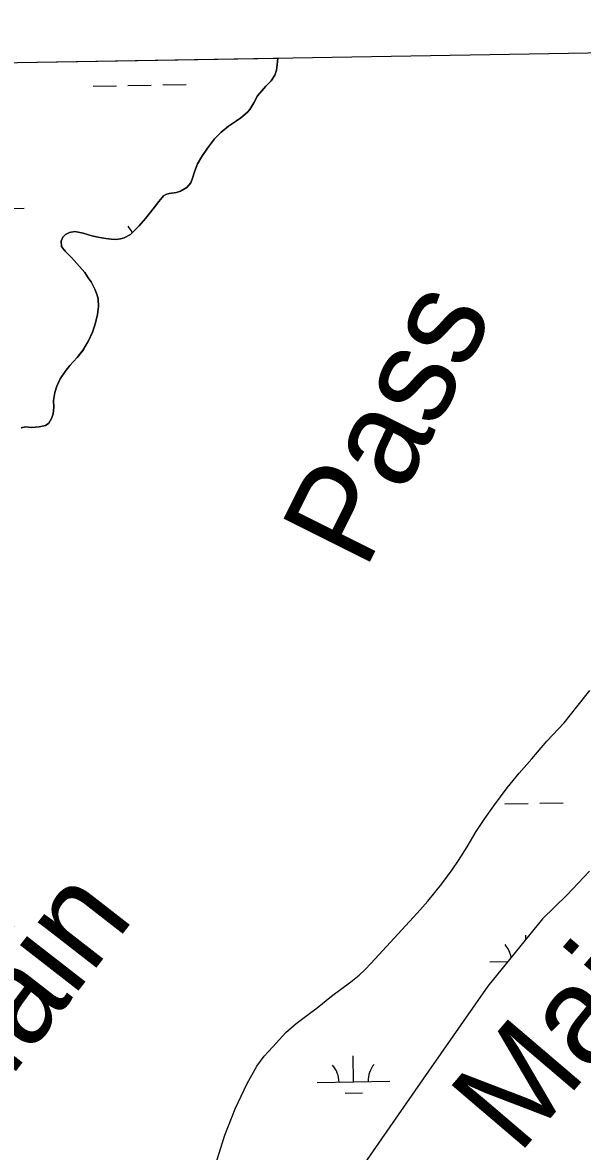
# Model space of a CAD drawing. Extents: x 3892998 to 3931244, y 278583 to 304547.
# Drawn here: x 3922438 to 3923209, y 301137 to 302691 of the extents above; entities that cross this region are included whole.
import ezdxf

# ---------------------------------------------------------------- set-up
doc = ezdxf.new("R2010")
doc.units = 0
for name, color, linetype in [('V-GRID-FRAM', 7, 'Continuous'), ('V-RIVR-IDEN', 7, 'Continuous'), ('V-TOPO-SHOR', 7, 'Continuous'), ('V-WETL-SWMP', 7, 'Continuous')]:
    doc.layers.add(name, color=color, linetype=linetype)

msp = doc.modelspace()

# ---------------------------------------------------------------- linework, layer by layer
at = {"layer": 'V-GRID-FRAM'}
msp.add_lwpolyline([(3896958.4, 302195.2), (3928823.6, 302746.7), (3929146.3, 284567.1), (3897265.1, 284015.2), (3896958.4, 302195.2)], dxfattribs=at)
at = {"layer": 'V-TOPO-SHOR'}
for points in [[(3922477.7, 302145.9), (3922479.7, 302152.3), (3922480.6, 302161.6), (3922480.2, 302170.5), (3922482.1, 302181.6), (3922485.1, 302190.5), (3922489.5, 302200.4), (3922496.3, 302210.7), (3922502.9, 302218.7), (3922512.7, 302229.7), (3922521.2, 302240.3), (3922528.1, 302252), (3922534.2, 302264.8), (3922537.7, 302275.9), (3922540.7, 302288.9), (3922542.3, 302300.2), (3922541.8, 302310.7), (3922540.1, 302317.3), (3922537.4, 302323.8), (3922532, 302334), (3922528.2, 302339.8), (3922523.4, 302347), (3922505.1, 302367.8), (3922496.5, 302376.1), (3922491.5, 302382.8), (3922490.8, 302389.9), (3922493.1, 302395.7), (3922496.9, 302399.5), (3922502.5, 302402.2), (3922509.5, 302403.4), (3922521.4, 302400.9), (3922533.3, 302397.4), (3922544.2, 302395), (3922552.4, 302393.9), (3922559.7, 302392.7), (3922566.1, 302392.2), (3922572.4, 302393.1), (3922577.8, 302394.8), (3922586.3, 302399.4), (3922598.4, 302411), (3922607, 302421.3), (3922619.3, 302436.8), (3922625.2, 302444.8), (3922630.1, 302450.4), (3922632, 302452.6), (3922635, 302454.4), (3922639.5, 302455.6), (3922649.5, 302457.1), (3922655.3, 302459), (3922663.8, 302464.1), (3922669.3, 302470.6), (3922671.1, 302475.3), (3922674.8, 302487), (3922678.8, 302496.7), (3922684.8, 302506.9), (3922692.5, 302518.3), (3922702.2, 302530.8), (3922710.8, 302539.7), (3922721.5, 302548.3), (3922732.2, 302555.6), (3922738.2, 302559.9), (3922747.5, 302567.6), (3922750.8, 302571.6), (3922756.3, 302580.6), (3922761.4, 302590.3), (3922767, 302597.2), (3922772.9, 302603.6), (3922780, 302611.1), (3922784.9, 302618.5), (3922787.3, 302625.6), (3922788.5, 302632.8), (3922789.1, 302642), (3922789.1, 302642.3)], [(3922436, 302132.9), (3922441.8, 302134.3), (3922450.3, 302133.6), (3922460.5, 302134.3), (3922469.5, 302136.3), (3922473.8, 302139.5), (3922477.7, 302145.9)], [(3922981.2, 301464.5), (3922995.7, 301481.3), (3923015.2, 301505.3), (3923029.4, 301524.5), (3923037.9, 301537), (3923049.9, 301555.9), (3923062.4, 301577.1), (3923074.1, 301594.9), (3923086.8, 301612.7), (3923105.2, 301637.3), (3923121.8, 301657.6), (3923138.9, 301677.4), (3923159.5, 301701.7), (3923183.6, 301727), (3923201, 301748.7), (3923218.7, 301771.4)], [(3923153.5, 301457), (3923187, 301489.4), (3923218.2, 301522.5)], [(3922700.6, 301109.3), (3922716.2, 301159), (3922730.3, 301195.4), (3922746.8, 301230.2), (3922760.1, 301253.8), (3922770.4, 301267.9), (3922782.2, 301280.8), (3922800.1, 301300.3), (3922814.6, 301312.7), (3922829.4, 301323.8), (3922843.4, 301334.2), (3922863, 301350.2), (3922889.6, 301370.1), (3922901.3, 301379.5), (3922909.4, 301387.2), (3922917.5, 301395.6), (3922928.4, 301407.1), (3922981.2, 301464.5)], [(3923153.5, 301457), (3923078.3, 301364.3), (3922996.9, 301246.9), (3922897.6, 301104.2)]]:
    msp.add_lwpolyline(points, dxfattribs=at)
at = {"layer": 'V-WETL-SWMP'}
for p, q in [((3922018.6, 302628.9), (3922789.1, 302642.3)), ((3922788.5, 302632.8), (3922787.3, 302625.6)), ((3922789.1, 302642), (3922788.5, 302632.8)), ((3922789.1, 302642.3), (3922789.1, 302642)), ((3922784.9, 302618.5), (3922780, 302611.1)), ((3922787.3, 302625.6), (3922784.9, 302618.5)), ((3922534.9, 302603.6), (3922566.9, 302604.1)), ((3922582.9, 302604.4), (3922614.9, 302604.9)), ((3922630.9, 302605.2), (3922662.9, 302605.8)), ((3922772.9, 302603.6), (3922767, 302597.2)), ((3922780, 302611.1), (3922772.9, 302603.6)), ((3922761.4, 302590.3), (3922756.3, 302580.6)), ((3922767, 302597.2), (3922761.4, 302590.3)), ((3922750.8, 302571.6), (3922747.5, 302567.6)), ((3922756.3, 302580.6), (3922750.8, 302571.6)), ((3922732.2, 302555.6), (3922721.5, 302548.3)), ((3922738.2, 302559.9), (3922732.2, 302555.6)), ((3922747.5, 302567.6), (3922738.2, 302559.9)), ((3922710.8, 302539.7), (3922702.2, 302530.8)), ((3922721.5, 302548.3), (3922710.8, 302539.7)), ((3922702.2, 302530.8), (3922692.5, 302518.3)), ((3922692.5, 302518.3), (3922684.8, 302506.9)), ((3922678.8, 302496.7), (3922674.8, 302487)), ((3922684.8, 302506.9), (3922678.8, 302496.7)), ((3922674.8, 302487), (3922671.1, 302475.3)), ((3922663.8, 302464.1), (3922655.3, 302459)), ((3922669.3, 302470.6), (3922663.8, 302464.1)), ((3922671.1, 302475.3), (3922669.3, 302470.6)), ((3922630.1, 302450.4), (3922625.2, 302444.8)), ((3922632, 302452.6), (3922630.1, 302450.4)), ((3922635, 302454.4), (3922632, 302452.6)), ((3922639.5, 302455.6), (3922635, 302454.4)), ((3922649.5, 302457.1), (3922639.5, 302455.6)), ((3922655.3, 302459), (3922649.5, 302457.1)), ((3922407.9, 302434.8), (3922439.9, 302435.4)), ((3922619.3, 302436.8), (3922607, 302421.3)), ((3922625.2, 302444.8), (3922619.3, 302436.8)), ((3922607, 302421.3), (3922598.4, 302411)), ((3922496.9, 302399.5), (3922493.1, 302395.7)), ((3922502.5, 302402.2), (3922496.9, 302399.5)), ((3922509.5, 302403.4), (3922502.5, 302402.2)), ((3922521.4, 302400.9), (3922509.5, 302403.4)), ((3922533.3, 302397.4), (3922521.4, 302400.9)), ((3922586.3, 302399.4), (3922577.8, 302394.8)), ((3922598.4, 302411), (3922586.3, 302399.4)), ((3922493.1, 302395.7), (3922490.8, 302389.9)), ((3922490.8, 302389.9), (3922491.5, 302382.8)), ((3922544.2, 302395), (3922533.3, 302397.4)), ((3922552.4, 302393.9), (3922544.2, 302395)), ((3922559.7, 302392.7), (3922552.4, 302393.9)), ((3922566.1, 302392.2), (3922559.7, 302392.7)), ((3922572.4, 302393.1), (3922566.1, 302392.2)), ((3922577.8, 302394.8), (3922572.4, 302393.1)), ((3922491.5, 302382.8), (3922496.5, 302376.1)), ((3922496.5, 302376.1), (3922505.1, 302367.8)), ((3922505.1, 302367.8), (3922523.4, 302347)), ((3922523.4, 302347), (3922528.2, 302339.8)), ((3922528.2, 302339.8), (3922532, 302334)), ((3922532, 302334), (3922537.4, 302323.8)), ((3922537.4, 302323.8), (3922540.1, 302317.3)), ((3922540.1, 302317.3), (3922541.8, 302310.7)), ((3922541.8, 302310.7), (3922542.3, 302300.2)), ((3922542.3, 302300.2), (3922540.7, 302288.9)), ((3922537.7, 302275.9), (3922534.2, 302264.8)), ((3922540.7, 302288.9), (3922537.7, 302275.9)), ((3922534.2, 302264.8), (3922528.1, 302252)), ((3922528.1, 302252), (3922521.2, 302240.2)), ((3922512.7, 302229.7), (3922502.9, 302218.7)), ((3922521.2, 302240.2), (3922512.7, 302229.7)), ((3922502.9, 302218.7), (3922496.3, 302210.7)), ((3922489.5, 302200.4), (3922485.1, 302190.5)), ((3922496.3, 302210.7), (3922489.5, 302200.4)), ((3922482.1, 302181.6), (3922480.2, 302170.5)), ((3922485.1, 302190.5), (3922482.1, 302181.6)), ((3922480.2, 302170.5), (3922480.6, 302161.6)), ((3922479.7, 302152.3), (3922477.7, 302145.9)), ((3922480.6, 302161.6), (3922479.7, 302152.3)), ((3922469.5, 302136.3), (3922460.5, 302134.3)), ((3922473.8, 302139.5), (3922469.5, 302136.3)), ((3922477.7, 302145.9), (3922473.8, 302139.5)), ((3922441.8, 302134.3), (3922436, 302132.9)), ((3922450.3, 302133.6), (3922441.8, 302134.3)), ((3922460.5, 302134.3), (3922450.3, 302133.6)), ((3923201, 301748.7), (3923218.7, 301771.4)), ((3923183.6, 301727), (3923201, 301748.7)), ((3923159.5, 301701.7), (3923183.6, 301727)), ((3923138.9, 301677.4), (3923159.5, 301701.7)), ((3923121.8, 301657.6), (3923138.9, 301677.4)), ((3923105.2, 301637.3), (3923121.8, 301657.6)), ((3923086.8, 301612.7), (3923105.2, 301637.3)), ((3923074.1, 301594.9), (3923086.8, 301612.7)), ((3923102, 301615.2), (3923134, 301615.7)), ((3923150, 301616), (3923182, 301616.6)), ((3923062.4, 301577.1), (3923074.1, 301594.9)), ((3923049.9, 301555.9), (3923062.4, 301577.1)), ((3923037.9, 301537), (3923049.9, 301555.9)), ((3923029.4, 301524.5), (3923037.9, 301537)), ((3923015.2, 301505.3), (3923029.4, 301524.5)), ((3923218.2, 301522.5), (3923187, 301489.4)), ((3922995.7, 301481.3), (3923015.2, 301505.3)), ((3923187, 301489.4), (3923153.5, 301457)), ((3922981.2, 301464.5), (3922995.7, 301481.3)), ((3922928.4, 301407.1), (3922981.2, 301464.5)), ((3923153.5, 301457), (3923078.3, 301364.3)), ((3923130.7, 301428.9), (3923130.6, 301434.4)), ((3922917.5, 301395.6), (3922928.4, 301407.1)), ((3922909.4, 301387.2), (3922917.5, 301395.6)), ((3923081.2, 301397.6), (3923105.6, 301398)), ((3922889.6, 301370.1), (3922901.3, 301379.5)), ((3922901.3, 301379.5), (3922909.4, 301387.2)), ((3922863, 301350.2), (3922889.6, 301370.1)), ((3923078.3, 301364.3), (3922996.9, 301246.9)), ((3922843.4, 301334.2), (3922863, 301350.2)), ((3922829.4, 301323.8), (3922843.4, 301334.2)), ((3922800.1, 301300.3), (3922814.6, 301312.7)), ((3922814.6, 301312.7), (3922829.4, 301323.8)), ((3922782.2, 301280.8), (3922800.1, 301300.3)), ((3922770.4, 301267.9), (3922782.2, 301280.8)), ((3922760.1, 301253.8), (3922770.4, 301267.9)), ((3922893.6, 301232.4), (3922892.9, 301268.4)), ((3922746.8, 301230.2), (3922760.1, 301253.8)), ((3922843.6, 301231.6), (3922943.5, 301233.3)), ((3922996.9, 301246.9), (3922897.6, 301104.2)), ((3922730.3, 301195.4), (3922746.8, 301230.2)), ((3922881.8, 301216.8), (3922905.8, 301217.2)), ((3922716.2, 301159), (3922730.3, 301195.4)), ((3922700.6, 301109.3), (3922716.2, 301159))]:
    msp.add_line(p, q, dxfattribs=at)
for centre, start, end in [((3922556.8, 302387.1), 24.6607, 41.7635), ((3923075.9, 301397.9), 10.1687, 41.7635), ((3922838.3, 301231.9), 0.2199, 41.7635), ((3922948.8, 301233.9), 140.2199, 181.7635)]:
    msp.add_arc(centre, 35.2, start, end, dxfattribs=at)

# ---------------------------------------------------------------- texts
at = {"layer": 'V-RIVR-IDEN'}
for s, rotation, p in [('Pass', 63.4351, (3922909.6, 301935.5)), ('Main', 52.125, (3922355.8, 301153.6)), ('Main', 49.5377, (3923120.4, 301130.4))]:
    msp.add_text(s, height=133, rotation=rotation, dxfattribs=at).set_placement(p)

doc.saveas('drawing.dxf')
